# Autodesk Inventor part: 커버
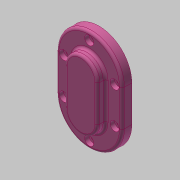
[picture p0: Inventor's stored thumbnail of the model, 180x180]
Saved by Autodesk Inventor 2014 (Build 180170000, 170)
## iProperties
Created: 2019-03
Part Number: 커버
Material: 알루미늄 6061
Document SubType Name: Modeling
Designer: mduedu
Density: 1 g/cm^3
Appearance: 분홍색
Author: mduedu
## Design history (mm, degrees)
sketch "스케치1"
  geometry: L1 (-62, 40)-(62, 40); L2 (62, 40)-(62, -40); L3 (62, -40)-(-62, -40); L4 (-62, -40)-(-62, 40); L5 (-62, 40)-(62, -40); L6 (62, 40)-(-62, -40); 1 further point
  constraints: 12 end point, 2 midpoint, 2 parallel, 1 horizontal, 1 perpendicular
  dimensions: "d59" = 124 distance of L2.end L3.end; "d60" = 80 distance of L1.end L2.end
extrude "돌출1" new body sketch "스케치1" distance "d4" = 12; taper "d5" = 0 deg
fillet "모깎기4"
fillet "모깎기5"
sketch "스케치2"
  geometry: L1 (-20, -22)-(20, -22); L2 (20, -22)-(20, 22); L3 (20, 22)-(-20, 22); L4 (-20, 22)-(-20, -22); L5 (-20, -22)-(20, 22); L6 (20, -22)-(-20, 22); 3 further points
  constraints: 12 end point, 4 midpoint, 2 horizontal alignment, 2 parallel, 1 horizontal, 1 perpendicular, 4 other
  dimensions: "d6" = 40 distance between parallel lines of L2 L4; "d8" = 44 distance between parallel lines of L1 L3
extrude "돌출2" join sketch "스케치2" distance "d9" = 10; taper "d10" = 0 deg
fillet "모깎기2" dims "d12" = 3
sketch "스케치3"
  geometry: L1 (-31, -22)-(31, -22); L2 (31, -22)-(31, 22); L3 (31, 22)-(-31, 22); L4 (-31, 22)-(-31, -22); L5 (-31, -22)-(31, 22); L6 (31, -22)-(-31, 22); A1 r 31 centre (0, 22) between (31, 22) and (0, 53); A2 r 31 centre (0, -22) between (31, -22) and (0, -53); 7 further points
  constraints: 12 end point, 6 midpoint, 4 coincident, 4 point on circle, 2 centre point, 2 parallel, 2 vertical alignment, 1 horizontal, 1 perpendicular
  dimensions: "d76" = 44 distance between parallel lines of L1 L3; "d78" = 62 distance between parallel lines of L2 L4
hole "구멍2" sketch "스케치3" at (0, 53), (31, 22), (31, -22), (-31, -22), (-31, 22), (0, -53) diameter "d28" = 5.5; stored, may be unused: countersink angle "d32" = 90 deg, drill point angle "d34" = 118 deg; dims "d29" = 6, "d30" = 4, "d31" = 2, "d33" = 8
sketch "스케치10"
  geometry: L1 (40, -22)-(40, 22) reference; L2 (-40, 22)-(-40, -22) reference; L3 (23, -22)-(23, 22) reference; L4 (-23, 22)-(-23, -22) reference; C1 r 2.75 at (-31, 22) reference; C2 r 2.75 at (31, -22) reference; C3 r 2.75 at (0, 53) reference; C4 r 2.75 at (31, 22) reference; C5 r 2.75 at (-31, -22) reference; C6 r 2.75 at (0, -53) reference; A1 r 40 centre (0, -22) between (-40, -22) and (40, -22) reference; A2 r 40 centre (0, 22) between (40, 22) and (-40, 22) reference; A3 r 23 centre (0, -22) between (-23, -22) and (23, -22) reference; A4 r 23 centre (0, 22) between (23, 22) and (-23, 22) reference; 7 further points
  constraints: 6 coincident
hole "구멍5" sketch "스케치10" at (0, 53), (31, 22), (31, -22), (0, -53), (-31, -22), (-31, 22) diameter "d79" = 11; stored, may be unused: countersink angle "d83" = 90 deg, drill point angle "d85" = 0 deg; dims "d80" = 6, "d81" = 4, "d82" = 2, "d84" = 5.4
fillet "모깎기3" dims "d68" = 3
sketch "스케치6"
  geometry: C1 r 12.5 at (0, 22); 1 further point
  constraints: 1 centre point, 1 vertical alignment
  dimensions: "d43" = 25 diameter of C1; "d45" = 22 distance of C1.centre point (0, 0)
extrude "돌출5" cut sketch "스케치6" distance "d47" = 15; taper "d48" = 0 deg
node "솔리드1"
mirror "대칭1"
node "투영된 루프5"
